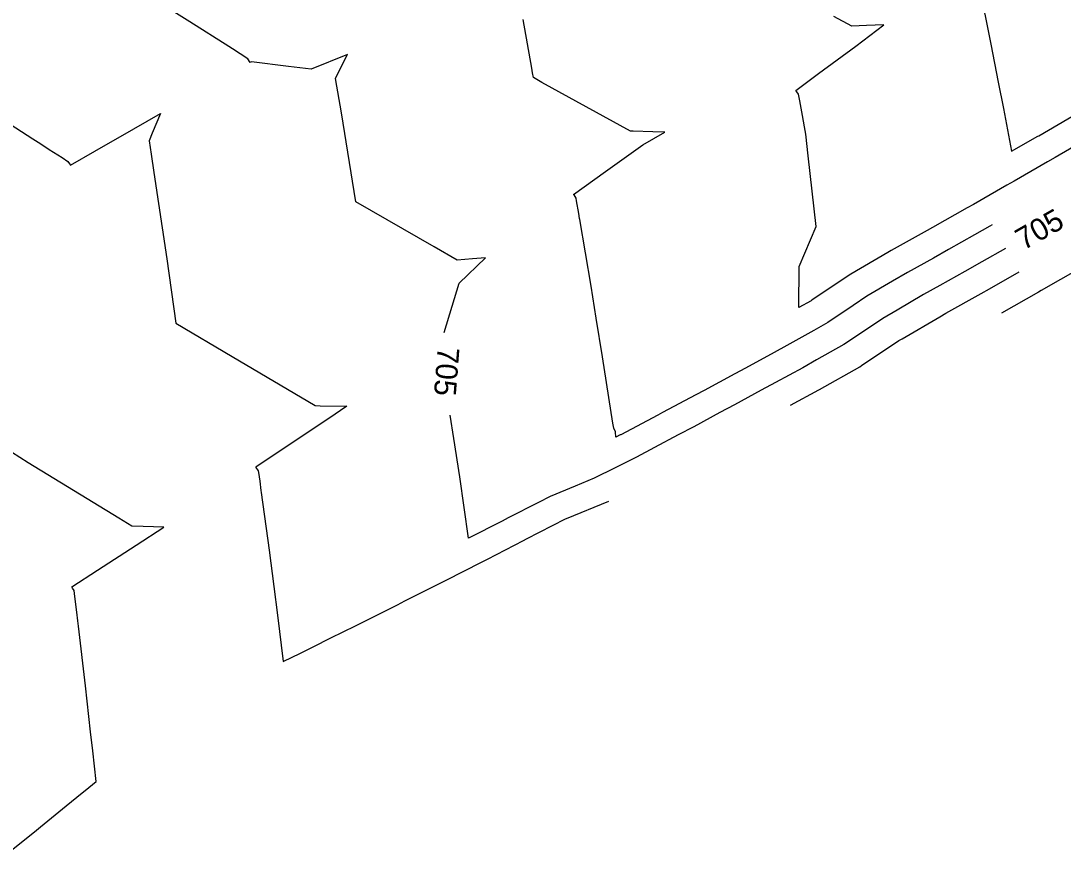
# Model space of a CAD drawing. Extents: x 1487507 to 1489130, y 497211 to 499439.
# Drawn here: x 1488223.8 to 1488338.2, y 498552.8 to 498644.2 of the extents above; entities that cross this region are included whole.
import ezdxf

# ---------------------------------------------------------------- set-up
doc = ezdxf.new("R2010")
doc.units = 0
for name, color, linetype in [('Prop CMT Ditch DDE', 7, 'Continuous'), ('Prop Drainage Ditch Flow Line', 7, 'Continuous'), ('Prop Drainage Structure Pipe Outlet Channel Detail CELL', 7, 'Continuous')]:
    doc.layers.add(name, color=color, linetype=linetype)

msp = doc.modelspace()

# ---------------------------------------------------------------- linework, layer by layer
at = {"layer": 'Prop CMT Ditch DDE'}
for points in [[(1488328.95, 498648.23), (1488330.28, 498641.61), (1488331.09, 498637.46), (1488331.67, 498634.55), (1488332.56, 498629.86), (1488335.43, 498631.51), (1488335.53, 498631.57), (1488339.78, 498634.03)], [(1488330.42, 498621.77), (1488330.15, 498621.62), (1488328.48, 498620.67), (1488325.64, 498619.06), (1488323.98, 498618.13), (1488321.12, 498616.53), (1488319.49, 498615.58), (1488316.66, 498613.93), (1488315.18, 498612.93), (1488312.39, 498611.06), (1488310.85, 498610.19), (1488307.89, 498608.52), (1488306.49, 498607.77), (1488303.34, 498606.05), (1488302.17, 498605.42), (1488298.79, 498603.6), (1488297.9, 498603.12), (1488294.23, 498601.16), (1488293.73, 498600.89), (1488289.67, 498598.73), (1488289.6, 498598.7), (1488289.11, 498598.45), (1488289.07, 498599.06), (1488288.91, 498599.44), (1488288.78, 498600), (1488287.65, 498607.28), (1488286.95, 498611.53), (1488286.39, 498615.06), (1488285.16, 498622.36), (1488285.14, 498622.47), (1488285.05, 498623.04), (1488284.81, 498624.43), (1488284.76, 498624.72), (1488284.52, 498625.07), (1488284.47, 498625.13), (1488287.98, 498627.62), (1488292.09, 498630.55), (1488294.5, 498631.97), (1488293.19, 498632), (1488291.01, 498632.05), (1488290.74, 498632.05), (1488281, 498637.43), (1488280.07, 498637.95), (1488279.98, 498638.48), (1488279.89, 498638.99), (1488278.94, 498644.35)], [(1488340.94, 498631.26), (1488337.34, 498629.17), (1488336.49, 498628.69), (1488332.85, 498626.59), (1488332.05, 498626.13), (1488328.36, 498624.03), (1488327.66, 498623.63), (1488323.86, 498621.48), (1488323.3, 498621.16), (1488319.35, 498618.95), (1488318.97, 498618.73), (1488314.89, 498616.35), (1488314.73, 498616.24), (1488310.63, 498613.49), (1488310.55, 498613.44), (1488309.21, 498612.69), (1488309.23, 498617.22), (1488311.09, 498621.58), (1488310.23, 498629.35), (1488309.98, 498631.74), (1488309.83, 498632.53), (1488309.6, 498633.79), (1488309.3, 498635.4), (1488309.16, 498636.15), (1488308.98, 498636.4), (1488308.86, 498636.55), (1488311.37, 498638.4), (1488315.44, 498641.41), (1488318.54, 498643.73), (1488316.62, 498643.66), (1488315.03, 498643.6), (1488313.03, 498644.65)], [(1488220.62, 498634.11), (1488225.13, 498631.21), (1488225.98, 498630.66), (1488226.91, 498630.06), (1488228.32, 498629.16), (1488228.96, 498628.75), (1488229.13, 498628.49), (1488229.24, 498628.34), (1488231.93, 498629.87), (1488236.21, 498632.34), (1488239.12, 498634.02), (1488238.22, 498631.85), (1488237.87, 498630.99), (1488238.09, 498629.53), (1488238.39, 498627.51), (1488239.81, 498618.05), (1488240.83, 498610.97), (1488246.98, 498607.3), (1488256.09, 498601.92), (1488256.65, 498601.91), (1488259.6, 498601.87), (1488257.59, 498600.52), (1488253.38, 498597.7), (1488249.59, 498595.18), (1488249.61, 498595.14), (1488249.86, 498594.76), (1488249.89, 498594.56), (1488250.02, 498593.61), (1488250.16, 498592.59), (1488250.18, 498592.38), (1488251.05, 498586.03), (1488251.56, 498582.05), (1488251.97, 498578.9), (1488252.61, 498573.82), (1488254.48, 498574.75), (1488255.9, 498575.44), (1488257.84, 498576.41), (1488260.53, 498577.74), (1488261.64, 498578.3), (1488265.15, 498580.06), (1488265.96, 498580.47), (1488269.77, 498582.39), (1488270.49, 498582.76), (1488274.38, 498584.74), (1488275.01, 498585.07), (1488278.98, 498587.1), (1488279.32, 498587.28), (1488283.59, 498589.47), (1488283.71, 498589.52), (1488288.34, 498591.42)], [(1488308.3, 498601.97), (1488311.38, 498603.65), (1488311.46, 498603.69), (1488315.9, 498606.19), (1488316.08, 498606.32), (1488320.19, 498609.07), (1488320.53, 498609.27), (1488324.67, 498611.69), (1488325.34, 498612.06), (1488329.2, 498614.24), (1488330.12, 498614.76), (1488333.37, 498616.6)], [(1488340.04, 498616.98), (1488335.81, 498614.56), (1488335.52, 498614.39), (1488331.44, 498612.08)], [(1488222.36, 498552.77), (1488225.52, 498555.31), (1488225.94, 498555.65), (1488228.78, 498557.95), (1488229.95, 498558.9), (1488231.28, 498559.99), (1488232.06, 498560.63), (1488231.7, 498564.01), (1488231.46, 498566.1), (1488230.9, 498571.16), (1488230.13, 498577.7), (1488230.06, 498578.29), (1488229.94, 498579.23), (1488229.74, 498580.94), (1488229.66, 498581.61), (1488229.48, 498581.89), (1488229.39, 498582.03), (1488232.21, 498583.84), (1488236.46, 498586.58), (1488239.51, 498588.56), (1488237.21, 498588.63), (1488236, 498588.67), (1488234.54, 498589.56), (1488231.75, 498591.27), (1488224.62, 498595.65), (1488220.89, 498597.97)]]:
    msp.add_lwpolyline(points, dxfattribs=at)
at = {"layer": 'Prop Drainage Ditch Flow Line'}
for points in [[(1488270.28, 498609.96), (1488271.15, 498612.85), (1488271.92, 498615.38), (1488274.81, 498618.14), (1488273.37, 498618.03), (1488271.71, 498617.91), (1488269.17, 498619.35), (1488260.56, 498624.3), (1488258.98, 498634.09), (1488258.35, 498637.86), (1488259.23, 498639.65), (1488259.64, 498640.49), (1488255.67, 498638.87), (1488253.17, 498639.18), (1488249.11, 498639.68), (1488248.99, 498639.62), (1488248.71, 498640.02), (1488248.71, 498640.03), (1488247.02, 498641.1), (1488246.63, 498641.35), (1488242.34, 498644.07), (1488238.44, 498646.57)], [(1488331.89, 498619.19), (1488329.3, 498617.72), (1488327.42, 498616.65), (1488324.66, 498615.1), (1488322.9, 498614.11), (1488320.01, 498612.42), (1488318.42, 498611.5), (1488315.63, 498609.62), (1488314.15, 498608.63), (1488311.15, 498606.94), (1488309.63, 498606.09), (1488306.64, 498604.45), (1488305.08, 498603.61), (1488302.14, 498602.02), (1488300.52, 498601.15), (1488297.66, 498599.61), (1488295.96, 498598.7), (1488293.34, 498597.31), (1488291.38, 498596.27), (1488289.03, 498595.09), (1488286.75, 498593.94), (1488284.66, 498593.08), (1488281.89, 498591.94), (1488280.64, 498591.3), (1488277.29, 498589.58), (1488276.63, 498589.24), (1488272.93, 498587.35), (1488271.97, 498594.11), (1488271.34, 498598.3), (1488270.94, 498600.88)]]:
    msp.add_lwpolyline(points, dxfattribs=at)

# ---------------------------------------------------------------- texts
at = {"layer": 'Prop Drainage Structure Pipe Outlet Channel Detail CELL'}
for rotation, p in [(29.7029, (1488333.87, 498618.94)), (265.5535, (1488269.56, 498608.42))]:
    msp.add_text('705', height=2.4, rotation=rotation, dxfattribs=at).set_placement(p)

doc.saveas('drawing.dxf')
